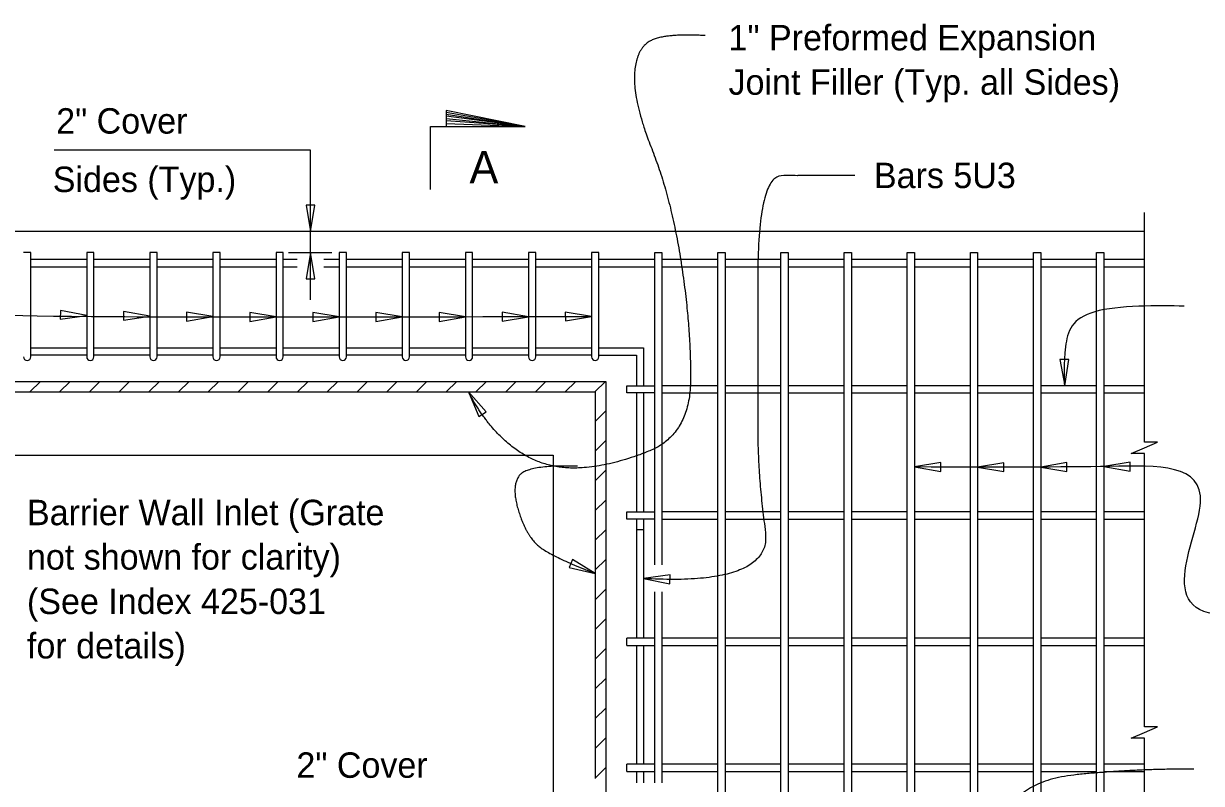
# Model space of a CAD drawing. Extents: x 120577.8 to 120649.9, y 120677.2 to 120721.6.
# Drawn here: x 120603.05 to 120612.38, y 120709.66 to 120715.68 of the extents above; entities that cross this region are included whole.
import ezdxf

# ---------------------------------------------------------------- set-up
doc = ezdxf.new("R2010")
doc.units = 0
for name, color, linetype in [('AdhocPoint_dp', 7, 'Continuous'), ('Border', 7, 'Continuous'), ('Patterning', 7, 'Continuous'), ('PlotBorder_dp', 7, 'Continuous'), ('TextMisc', 7, 'Continuous')]:
    doc.layers.add(name, color=color, linetype=linetype)

msp = doc.modelspace()

# ---------------------------------------------------------------- linework, layer by layer
at = {"layer": 'Border'}
for p, q in [((120602.5808, 120712.7572), (120607.5808, 120712.7572)), ((120603.1025, 120712.7572), (120603.1858, 120712.8405)), ((120603.3381, 120712.7572), (120603.4214, 120712.8405)), ((120603.5736, 120712.7572), (120603.6569, 120712.8405)), ((120603.8092, 120712.7572), (120603.8925, 120712.8405)), ((120604.0447, 120712.7572), (120604.128, 120712.8405)), ((120604.2803, 120712.7572), (120604.3636, 120712.8405)), ((120604.5158, 120712.7572), (120604.5991, 120712.8405)), ((120604.7514, 120712.7572), (120604.8347, 120712.8405)), ((120604.9869, 120712.7572), (120605.0702, 120712.8405)), ((120605.2225, 120712.7572), (120605.3058, 120712.8405)), ((120605.4581, 120712.7572), (120605.5414, 120712.8405)), ((120605.6936, 120712.7572), (120605.7769, 120712.8405)), ((120605.9292, 120712.7572), (120606.0125, 120712.8405)), ((120606.1647, 120712.7572), (120606.248, 120712.8405)), ((120606.4003, 120712.7572), (120606.4836, 120712.8405)), ((120606.6358, 120712.7572), (120606.7191, 120712.8405)), ((120606.8714, 120712.7572), (120606.9547, 120712.8405)), ((120607.1069, 120712.7572), (120607.1902, 120712.8405)), ((120607.3425, 120712.7572), (120607.4258, 120712.8405)), ((120607.5781, 120712.7572), (120607.6614, 120712.8405)), ((120607.5808, 120712.7572), (120607.5808, 120709.6954)), ((120607.5808, 120712.5242), (120607.6641, 120712.6075)), ((120607.5808, 120712.2888), (120607.6641, 120712.3721)), ((120602.9141, 120712.2572), (120607.2474, 120712.2572)), ((120607.2474, 120712.2572), (120607.2474, 120708.5072)), ((120607.5808, 120712.0532), (120607.6641, 120712.1365)), ((120607.5808, 120711.8176), (120607.6641, 120711.9009)), ((120607.5808, 120711.5821), (120607.6641, 120711.6654)), ((120607.5808, 120711.3465), (120607.6641, 120711.4298)), ((120607.5808, 120711.111), (120607.6641, 120711.1943)), ((120607.5808, 120710.8754), (120607.6641, 120710.9587)), ((120607.5808, 120710.6399), (120607.6641, 120710.7232)), ((120607.5808, 120710.4043), (120607.6641, 120710.4876)), ((120607.5808, 120710.1688), (120607.6641, 120710.2521)), ((120607.5808, 120709.9332), (120607.6641, 120710.0165)), ((120607.5808, 120709.6977), (120607.6641, 120709.781))]:
    msp.add_line(p, q, dxfattribs=at)
at = {"layer": 'Patterning'}
for p, q in [((120603.1094, 120713.8614), (120603.0521, 120713.8614)), ((120603.1094, 120713.0358), (120603.1094, 120713.8614)), ((120603.6094, 120713.8614), (120603.5521, 120713.8614)), ((120603.5521, 120713.8614), (120603.5521, 120713.0358)), ((120603.6094, 120713.0358), (120603.6094, 120713.8614)), ((120604.1094, 120713.8614), (120604.0521, 120713.8614)), ((120604.0521, 120713.8614), (120604.0521, 120713.0358)), ((120604.1094, 120713.0358), (120604.1094, 120713.8614)), ((120604.6094, 120713.8614), (120604.5521, 120713.8614)), ((120604.5521, 120713.8614), (120604.5521, 120713.0358)), ((120604.6094, 120713.0358), (120604.6094, 120713.8614)), ((120605.1094, 120713.8614), (120605.0521, 120713.8614)), ((120605.0521, 120713.8614), (120605.0521, 120713.0358)), ((120605.1094, 120713.0358), (120605.1094, 120713.8614)), ((120605.6094, 120713.8614), (120605.5521, 120713.8614)), ((120605.5521, 120713.8614), (120605.5521, 120713.0358)), ((120605.6094, 120713.0358), (120605.6094, 120713.8614)), ((120606.1094, 120713.8614), (120606.0521, 120713.8614)), ((120606.0521, 120713.8614), (120606.0521, 120713.0358)), ((120606.1094, 120713.0358), (120606.1094, 120713.8614)), ((120606.6094, 120713.8614), (120606.5521, 120713.8614)), ((120606.5521, 120713.8614), (120606.5521, 120713.0358)), ((120606.6094, 120713.0358), (120606.6094, 120713.8614)), ((120607.1094, 120713.8614), (120607.0521, 120713.8614)), ((120607.0521, 120713.8614), (120607.0521, 120713.0358)), ((120607.1094, 120713.0358), (120607.1094, 120713.8614)), ((120607.6094, 120713.8614), (120607.5521, 120713.8614)), ((120607.5521, 120713.8614), (120607.5521, 120713.0358)), ((120607.6094, 120713.0358), (120607.6094, 120713.8614)), ((120608.0521, 120713.8614), (120608.1094, 120713.8614)), ((120608.0521, 120711.3865), (120608.0521, 120713.8614)), ((120608.1094, 120713.8614), (120608.1094, 120711.3865)), ((120608.5521, 120707.2437), (120608.5521, 120713.8614)), ((120608.5521, 120713.8614), (120608.6094, 120713.8614)), ((120608.6094, 120713.8614), (120608.6094, 120707.9744)), ((120609.0521, 120707.2437), (120609.0521, 120713.8614)), ((120609.0521, 120713.8614), (120609.1094, 120713.8614)), ((120609.1094, 120713.8614), (120609.1094, 120707.9744)), ((120609.5521, 120707.2437), (120609.5521, 120713.8614)), ((120609.5521, 120713.8614), (120609.6094, 120713.8614)), ((120609.6094, 120713.8614), (120609.6094, 120707.9744)), ((120610.0521, 120707.2437), (120610.0521, 120713.8614)), ((120610.0521, 120713.8614), (120610.1094, 120713.8614)), ((120610.1094, 120713.8614), (120610.1094, 120707.9744)), ((120610.5521, 120707.2437), (120610.5521, 120713.8614)), ((120610.5521, 120713.8614), (120610.6094, 120713.8614)), ((120610.6094, 120713.8614), (120610.6094, 120707.9744)), ((120611.0521, 120707.2437), (120611.0521, 120713.8614)), ((120611.0521, 120713.8614), (120611.1094, 120713.8614)), ((120611.1094, 120713.8614), (120611.1094, 120707.9744)), ((120611.5521, 120713.8614), (120611.6094, 120713.8614)), ((120611.5521, 120707.2437), (120611.5521, 120713.8614)), ((120611.6094, 120713.8614), (120611.6094, 120707.9744)), ((120607.6094, 120713.0488), (120607.9068, 120713.0488)), ((120607.9068, 120713.0488), (120607.9068, 120712.8067)), ((120607.9641, 120713.1061), (120607.9641, 120712.8067)), ((120607.8307, 120712.7494), (120607.8307, 120712.8067)), ((120607.9068, 120712.7494), (120607.9068, 120711.8067)), ((120607.9641, 120712.7494), (120607.9641, 120711.8067)), ((120607.8307, 120711.7494), (120607.8307, 120711.8067)), ((120607.9068, 120711.7494), (120607.9068, 120710.8067)), ((120607.9641, 120711.7494), (120607.9641, 120710.8067)), ((120607.9641, 120711.6655), (120607.9068, 120711.6655)), ((120608.0521, 120709.6603), (120608.0521, 120711.1724)), ((120608.1094, 120711.1724), (120608.1094, 120709.6603)), ((120607.8307, 120710.7494), (120607.8307, 120710.8067)), ((120607.9068, 120710.7494), (120607.9068, 120709.8067)), ((120607.9641, 120710.7494), (120607.9641, 120709.8067)), ((120607.8307, 120709.7494), (120607.8307, 120709.8067)), ((120607.9068, 120709.7494), (120607.9068, 120709.6603)), ((120607.9641, 120709.7494), (120607.9641, 120709.6603))]:
    msp.add_line(p, q, dxfattribs=at)
for points in [[(120603.5521, 120713.8067), (120603.1094, 120713.8067)], [(120604.0521, 120713.8067), (120603.6094, 120713.8067)], [(120604.5521, 120713.8067), (120604.1094, 120713.8067)], [(120605.0521, 120713.8067), (120604.6094, 120713.8067)], [(120605.2184, 120713.8067), (120605.1094, 120713.8067)], [(120605.5521, 120713.8067), (120605.4308, 120713.8067)], [(120606.0521, 120713.8067), (120605.6094, 120713.8067)], [(120606.5521, 120713.8067), (120606.1094, 120713.8067)], [(120607.0521, 120713.8067), (120606.6094, 120713.8067)], [(120607.5521, 120713.8067), (120607.1094, 120713.8067)], [(120608.0521, 120713.8067), (120607.6094, 120713.8067)], [(120608.5521, 120713.8067), (120608.1094, 120713.8067)], [(120609.0521, 120713.8067), (120608.6094, 120713.8067)], [(120609.5521, 120713.8067), (120609.1094, 120713.8067)], [(120610.0521, 120713.8067), (120609.6094, 120713.8067)], [(120610.5521, 120713.8067), (120610.1094, 120713.8067)], [(120611.0521, 120713.8067), (120610.6094, 120713.8067)], [(120611.5521, 120713.8067), (120611.1094, 120713.8067)], [(120611.9308, 120713.8067), (120611.6094, 120713.8067)], [(120603.1094, 120713.7494), (120603.5521, 120713.7494)], [(120603.6094, 120713.7494), (120604.0521, 120713.7494)], [(120604.1094, 120713.7494), (120604.5521, 120713.7494)], [(120604.6094, 120713.7494), (120605.0521, 120713.7494)], [(120605.1094, 120713.7494), (120605.2184, 120713.7494)], [(120605.4308, 120713.7494), (120605.5521, 120713.7494)], [(120605.6094, 120713.7494), (120606.0521, 120713.7494)], [(120606.1094, 120713.7494), (120606.5521, 120713.7494)], [(120606.6094, 120713.7494), (120607.0521, 120713.7494)], [(120607.1094, 120713.7494), (120607.5521, 120713.7494)], [(120607.6094, 120713.7494), (120608.0521, 120713.7494)], [(120608.1094, 120713.7494), (120608.5521, 120713.7494)], [(120608.6094, 120713.7494), (120609.0521, 120713.7494)], [(120609.1094, 120713.7494), (120609.5521, 120713.7494)], [(120609.6094, 120713.7494), (120610.0521, 120713.7494)], [(120610.1094, 120713.7494), (120610.5521, 120713.7494)], [(120610.6094, 120713.7494), (120611.0521, 120713.7494)], [(120611.1094, 120713.7494), (120611.5521, 120713.7494)], [(120611.6094, 120713.7494), (120611.9308, 120713.7494)], [(120603.1094, 120713.1061), (120603.5521, 120713.1061)], [(120603.5521, 120713.0488), (120603.1094, 120713.0488)], [(120603.6094, 120713.1061), (120604.0521, 120713.1061)], [(120604.0521, 120713.0488), (120603.6094, 120713.0488)], [(120604.1094, 120713.1061), (120604.5521, 120713.1061)], [(120604.5521, 120713.0488), (120604.1094, 120713.0488)], [(120604.6094, 120713.1061), (120605.0521, 120713.1061)], [(120605.0521, 120713.0488), (120604.6094, 120713.0488)], [(120605.1094, 120713.1061), (120605.5521, 120713.1061)], [(120605.5521, 120713.0488), (120605.1094, 120713.0488)], [(120605.6094, 120713.1061), (120606.0521, 120713.1061)], [(120606.0521, 120713.0488), (120605.6094, 120713.0488)], [(120606.1094, 120713.1061), (120606.5521, 120713.1061)], [(120606.5521, 120713.0488), (120606.1094, 120713.0488)], [(120606.6094, 120713.1061), (120607.0521, 120713.1061)], [(120607.0521, 120713.0488), (120606.6094, 120713.0488)], [(120607.1094, 120713.1061), (120607.5521, 120713.1061)], [(120607.5521, 120713.0488), (120607.1094, 120713.0488)], [(120607.6094, 120713.1061), (120607.9641, 120713.1061)], [(120607.8307, 120712.8067), (120608.0521, 120712.8067)], [(120608.5521, 120712.8067), (120608.1094, 120712.8067)], [(120609.0521, 120712.8067), (120608.6094, 120712.8067)], [(120609.5521, 120712.8067), (120609.1094, 120712.8067)], [(120610.0521, 120712.8067), (120609.6094, 120712.8067)], [(120610.5521, 120712.8067), (120610.1094, 120712.8067)], [(120611.0521, 120712.8067), (120610.6094, 120712.8067)], [(120611.5521, 120712.8067), (120611.1094, 120712.8067)], [(120611.9308, 120712.8067), (120611.6094, 120712.8067)], [(120608.0521, 120712.7494), (120607.8307, 120712.7494)], [(120608.1094, 120712.7494), (120608.5521, 120712.7494)], [(120608.6094, 120712.7494), (120609.0521, 120712.7494)], [(120609.1094, 120712.7494), (120609.5521, 120712.7494)], [(120609.6094, 120712.7494), (120610.0521, 120712.7494)], [(120610.1094, 120712.7494), (120610.5521, 120712.7494)], [(120610.6094, 120712.7494), (120611.0521, 120712.7494)], [(120611.1094, 120712.7494), (120611.5521, 120712.7494)], [(120611.6094, 120712.7494), (120611.9308, 120712.7494)], [(120607.8307, 120711.8067), (120608.0521, 120711.8067)], [(120608.0521, 120711.7494), (120607.8307, 120711.7494)], [(120608.5521, 120711.8067), (120608.1094, 120711.8067)], [(120608.1094, 120711.7494), (120608.5521, 120711.7494)], [(120609.0521, 120711.8067), (120608.6094, 120711.8067)], [(120608.6094, 120711.7494), (120609.0521, 120711.7494)], [(120609.5521, 120711.8067), (120609.1094, 120711.8067)], [(120609.1094, 120711.7494), (120609.5521, 120711.7494)], [(120610.0521, 120711.8067), (120609.6094, 120711.8067)], [(120609.6094, 120711.7494), (120610.0521, 120711.7494)], [(120610.5521, 120711.8067), (120610.1094, 120711.8067)], [(120610.1094, 120711.7494), (120610.5521, 120711.7494)], [(120611.0521, 120711.8067), (120610.6094, 120711.8067)], [(120610.6094, 120711.7494), (120611.0521, 120711.7494)], [(120611.5521, 120711.8067), (120611.1094, 120711.8067)], [(120611.1094, 120711.7494), (120611.5521, 120711.7494)], [(120611.9308, 120711.8067), (120611.6094, 120711.8067)], [(120611.6094, 120711.7494), (120611.9308, 120711.7494)], [(120608.0521, 120710.8067), (120607.8307, 120710.8067)], [(120608.5521, 120710.8067), (120608.1094, 120710.8067)], [(120609.0521, 120710.8067), (120608.6094, 120710.8067)], [(120609.5521, 120710.8067), (120609.1094, 120710.8067)], [(120610.0521, 120710.8067), (120609.6094, 120710.8067)], [(120610.5521, 120710.8067), (120610.1094, 120710.8067)], [(120611.0521, 120710.8067), (120610.6094, 120710.8067)], [(120611.5521, 120710.8067), (120611.1094, 120710.8067)], [(120611.9308, 120710.8067), (120611.6094, 120710.8067)], [(120607.8307, 120710.7494), (120608.0521, 120710.7494)], [(120608.1094, 120710.7494), (120608.5521, 120710.7494)], [(120608.6094, 120710.7494), (120609.0521, 120710.7494)], [(120609.1094, 120710.7494), (120609.5521, 120710.7494)], [(120609.6094, 120710.7494), (120610.0521, 120710.7494)], [(120610.1094, 120710.7494), (120610.5521, 120710.7494)], [(120610.6094, 120710.7494), (120611.0521, 120710.7494)], [(120611.1094, 120710.7494), (120611.5521, 120710.7494)], [(120611.6094, 120710.7494), (120611.9308, 120710.7494)], [(120608.0521, 120709.8067), (120607.8307, 120709.8067)], [(120608.5521, 120709.8067), (120608.1094, 120709.8067)], [(120609.0521, 120709.8067), (120608.6094, 120709.8067)], [(120609.5521, 120709.8067), (120609.1094, 120709.8067)], [(120610.0521, 120709.8067), (120609.6094, 120709.8067)], [(120610.5521, 120709.8067), (120610.1094, 120709.8067)], [(120611.0521, 120709.8067), (120610.6094, 120709.8067)], [(120611.5521, 120709.8067), (120611.1094, 120709.8067)], [(120611.9308, 120709.8067), (120611.6094, 120709.8067)], [(120607.8307, 120709.7494), (120608.0521, 120709.7494)], [(120608.1094, 120709.7494), (120608.5521, 120709.7494)], [(120608.6094, 120709.7494), (120609.0521, 120709.7494)], [(120609.1094, 120709.7494), (120609.5521, 120709.7494)], [(120609.6094, 120709.7494), (120610.0521, 120709.7494)], [(120610.1094, 120709.7494), (120610.5521, 120709.7494)], [(120610.6094, 120709.7494), (120611.0521, 120709.7494)], [(120611.1094, 120709.7494), (120611.5521, 120709.7494)], [(120611.6094, 120709.7494), (120611.9308, 120709.7494)]]:
    msp.add_lwpolyline(points, dxfattribs=at)
for centre in [(120603.0808, 120713.0358), (120603.5808, 120713.0358), (120604.0808, 120713.0358), (120604.5808, 120713.0358), (120605.0808, 120713.0358), (120605.5808, 120713.0358), (120606.0808, 120713.0358), (120606.5808, 120713.0358), (120607.0808, 120713.0358), (120607.5808, 120713.0358)]:
    msp.add_arc(centre, 0.0286, 180, 0, dxfattribs=at)
at = {"layer": 'PlotBorder_dp'}
for p, q in [((120607.0251, 120714.8617), (120606.4001, 120714.9717)), ((120606.4001, 120714.9584), (120607.0251, 120714.8617)), ((120607.0251, 120714.8617), (120606.4001, 120714.9417)), ((120606.4001, 120714.9234), (120607.0251, 120714.8617)), ((120607.0251, 120714.8617), (120606.4001, 120714.9051)), ((120606.4001, 120714.8851), (120607.0251, 120714.8617)), ((120605.3252, 120714.6732), (120603.2953, 120714.6732)), ((120605.3252, 120713.4861), (120605.3252, 120714.6732)), ((120605.1507, 120713.8614), (120605.4944, 120713.8614))]:
    msp.add_line(p, q, dxfattribs=at)
for points in [[(120606.2751, 120714.3617), (120606.2751, 120714.8617), (120607.0251, 120714.8617), (120606.4001, 120714.9867), (120606.4001, 120714.8617)], [(120611.9307, 120710.7494), (120611.9307, 120712.2689), (120611.8274, 120712.2689), (120611.9307, 120712.3139), (120612.0341, 120712.3589), (120611.9307, 120712.3589), (120611.9307, 120714.178)], [(120611.9307, 120708.4239), (120611.9307, 120710.0138), (120611.8274, 120710.0138), (120611.9307, 120710.0588), (120612.0341, 120710.1038), (120611.9307, 120710.1038), (120611.9307, 120710.7494)]]:
    msp.add_lwpolyline(points, dxfattribs=at)
for points in [[(120605.3252, 120714.0281), (120605.3604, 120714.2363), (120605.2899, 120714.2363)], [(120605.3252, 120713.8614), (120605.2899, 120713.6532), (120605.3604, 120713.6532)], [(120603.5521, 120713.3643), (120603.3446, 120713.4036), (120603.3432, 120713.333)], [(120604.0521, 120713.3577), (120603.8442, 120713.3953), (120603.8434, 120713.3248)], [(120604.5521, 120713.354), (120604.3437, 120713.3884), (120604.344, 120713.3178)], [(120605.0521, 120713.352), (120604.8437, 120713.3864), (120604.844, 120713.3158)], [(120605.5521, 120713.3512), (120605.3437, 120713.3856), (120605.344, 120713.315)], [(120606.0521, 120713.3514), (120605.8437, 120713.3857), (120605.844, 120713.3152)], [(120606.5521, 120713.3522), (120606.3437, 120713.3866), (120606.344, 120713.3161)], [(120607.0521, 120713.3537), (120606.8437, 120713.3881), (120606.844, 120713.3175)], [(120607.5521, 120713.3556), (120607.3437, 120713.39), (120607.344, 120713.3195)], [(120611.3005, 120712.8067), (120611.332, 120713.0155), (120611.2614, 120713.0142)], [(120606.5768, 120712.7572), (120606.6583, 120712.5623), (120606.7179, 120712.6)], [(120610.1094, 120712.1627), (120610.3175, 120712.1267), (120610.3177, 120712.1973)], [(120610.6094, 120712.1614), (120610.8176, 120712.1258), (120610.8177, 120712.1963)], [(120611.1094, 120712.1615), (120611.3178, 120712.1275), (120611.3174, 120712.198)], [(120611.6094, 120712.1658), (120611.8174, 120712.1292), (120611.8178, 120712.1998)], [(120607.5807, 120711.3188), (120607.4016, 120711.4308), (120607.3747, 120711.3655)], [(120607.9641, 120711.2781), (120608.1714, 120711.2379), (120608.1731, 120711.3085)]]:
    msp.add_lwpolyline(points, close=True, dxfattribs=at)
for points, degree in [([(120608.4528, 120715.5808), (120608.0925, 120715.602), (120607.8911, 120715.4429), (120607.8911, 120715.0291), (120608.1773, 120714.3077), (120608.3362, 120713.3105), (120608.3362, 120712.4194), (120607.6685, 120712.1541), (120607.1492, 120712.1541), (120606.7252, 120712.4724), (120606.5769, 120712.7572)], 2), ([(120602.0274, 120714.7135), (120602.3163, 120714.7241), (120602.4593, 120714.5968), (120602.4673, 120714.3157), (120602.2527, 120713.6845), (120602.2527, 120713.4511), (120602.56, 120713.3344), (120607.5521, 120713.3556)], 2), ([(120609.6381, 120714.471), (120609.2531, 120714.471), (120608.8681, 120714.471), (120608.8681, 120712.8454), (120608.8681, 120712.0868), (120608.9885, 120711.2212), (120607.9641, 120711.278)], 2), ([(120612.245, 120713.4358), (120612.0483, 120713.4437), (120611.3912, 120713.4437), (120611.286, 120713.1354), (120611.2953, 120712.8452), (120611.297, 120712.8067)], 3), ([(120607.4407, 120712.1687), (120607.0432, 120712.1806), (120606.9146, 120712.0078), (120607.0276, 120711.6344), (120607.2085, 120711.4627), (120607.5808, 120711.3188)], 2), ([(120612.6437, 120710.9919), (120611.9731, 120710.9508), (120612.7392, 120712.1991), (120611.7032, 120712.161), (120610.8263, 120712.1603), (120610.1094, 120712.1626)], 3), ([(120612.3221, 120709.7695), (120611.8565, 120709.7695), (120610.9828, 120709.6849), (120610.7772, 120709.2432), (120610.7893, 120708.4238)], 2)]:
    msp.add_open_spline(points, degree=degree, dxfattribs=at)
at = {"layer": 'TextMisc'}
for p, q in [((120611.9308, 120714.028), (120598.2308, 120714.028)), ((120602.4975, 120712.8405), (120607.6641, 120712.8405)), ((120607.6641, 120712.8405), (120607.6641, 120708.4238))]:
    msp.add_line(p, q, dxfattribs=at)

# ---------------------------------------------------------------- texts
at = {"layer": 'AdhocPoint_dp'}
for s, height, p in [('2" Cover', 0.2016, (120603.3107, 120714.804)), ('A', 0.256, (120606.5846, 120714.4108)), ('Sides (Typ.)', 0.2016, (120603.2834, 120714.3411)), ('Bars 5U3', 0.2016, (120609.7885, 120714.3723)), ('2" Cover', 0.2016, (120605.2136, 120709.6997))]:
    msp.add_text(s, height=height, dxfattribs=at).set_placement(p)
at = {"layer": 'PlotBorder_dp'}
for s, p in [('1" Preformed Expansion ', (120608.6368, 120715.464)), ('Joint Filler (Typ. all Sides)', (120608.6368, 120715.112)), ('Barrier Wall Inlet (Grate ', (120603.0792, 120711.7014)), ('not shown for clarity)  ', (120603.0792, 120711.3494)), ('(See Index 425-031', (120603.0792, 120710.9974)), ('for details)', (120603.0792, 120710.6454))]:
    msp.add_text(s, height=0.2016, dxfattribs=at).set_placement(p)

doc.saveas('drawing.dxf')
